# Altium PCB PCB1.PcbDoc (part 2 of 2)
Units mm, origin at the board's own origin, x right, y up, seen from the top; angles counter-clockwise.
Board outline 82.55 x 101.6 mm, 4 copper layers (Top Layer, GND, POWER, Bottom Layer), stack 1.586 mm thick; 125 components, 82 nets, 451 pads, 255 vias.
Unrouted connection lines stored in the file: 4.
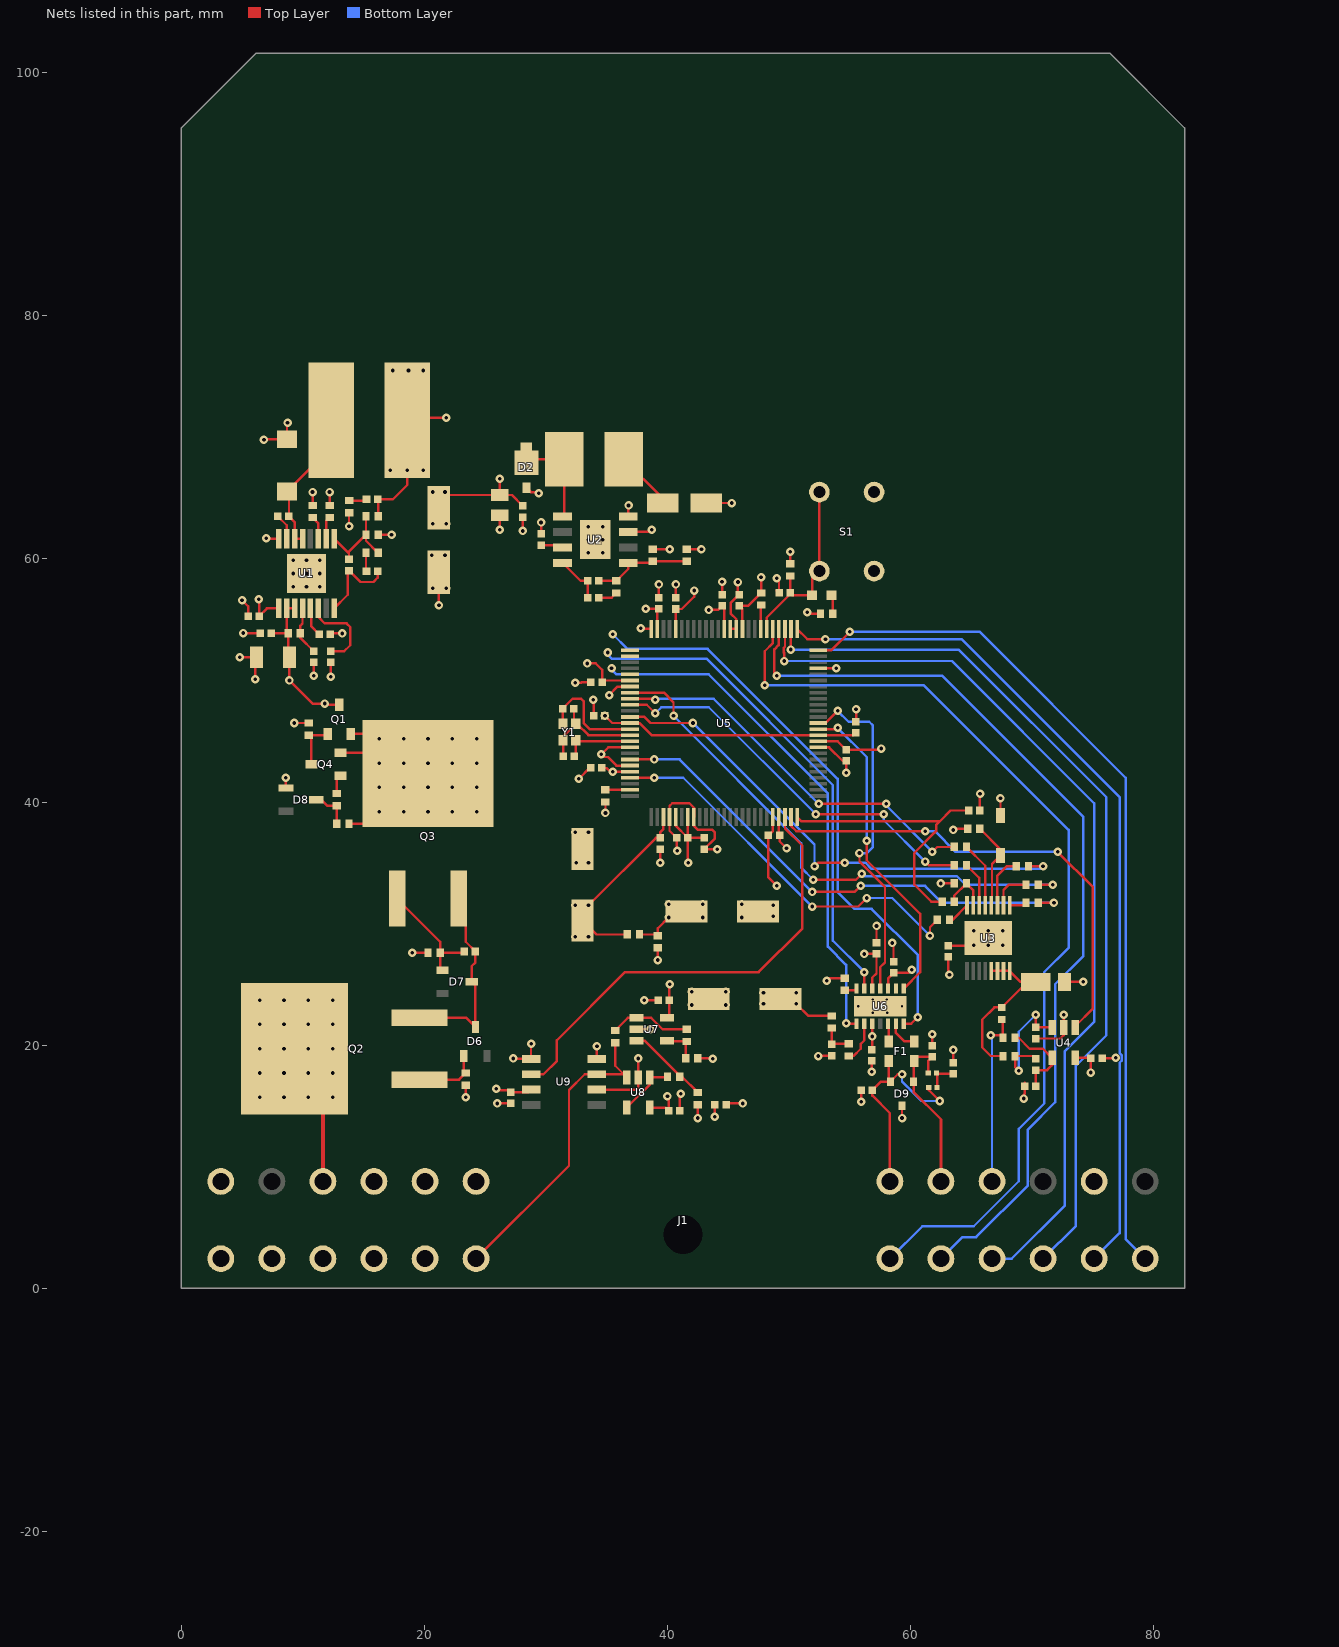
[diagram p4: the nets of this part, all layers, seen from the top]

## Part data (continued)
R31 R32: library part RK73H1HRTTCM60R4F, "Fixed Resistor, Metal Glaze/thick Film, 0.05W, 60.4ohm, 25V, 1% +/-Tol, 300ppm/Cel, Surface Mount, 0201", Manufacturer="KOA Speer", Supplier Part Number=660-RK73H1HRTTCM60R4
R33: library part AC0402FR-076K2L, "Fixed Resistor, Metal Glaze/thick Film, 0.0625W, 6200ohm, 50V, 1% +/-Tol, 100ppm/Cel, Surface Mount, 0402", Case/Package=0402, Manufacturer=Yageo, Max Operating Temperature=155°C, Min Operating Temperature=-55°C, Package Height=0.32mm, Package Length=1mm, Package Shape=Rectangular, Package Width=0.5mm, Power=62.5mW, Rated Temperature=70°C, Resistor Type="FIXED RESISTOR", Supplier Part Number=603-AC0402FR-076K2L, Temperature Coefficient (ppm/Cel)=100, Tolerance=1%, Working Voltage=50V
R34: library part RC0402JR-072KP, "Fixed Resistor, Metal Glaze/thick Film, 0.0625W, 2000ohm, 50V, 5% +/-Tol, 150ppm/Cel, Surface Mount, 0402", Manufacturer=Yageo, Supplier Part Number=603-RC0402JR-072KP
R36 R37: library part AC0402FR-1010RL, "Fixed Resistor, Metal Glaze/thick Film, 0.0625W, 10ohm, 50V, 1% +/-Tol, 200ppm/Cel, Surface Mount, 0402", Case/Package=0402, Manufacturer=Yageo, Max Operating Temperature=155°C, Min Operating Temperature=-55°C, Package Height=0.32mm, Package Length=1mm, Package Shape=Rectangular, Package Width=0.5mm, Power=62.5mW, Rated Temperature=70°C, Resistor Type="FIXED RESISTOR", Supplier Part Number=603-AC0402FR-1010RL, Temperature Coefficient (ppm/Cel)=200, Tolerance=1%, Working Voltage=50V
S1: "BUTON MINI 6X6X5, 4 PINI"
U1: library part A7987TR, "Switching Regulator, Voltage-mode, 4.4A, 1650kHz Switching Freq-Max, PDSO16", Manufacturer=STMicroelectronics, Supplier Part Number=511-A7987TR
U2: library part A7985ATR, "Switching Regulator, Voltage-mode, 3.5A, 275kHz Switching Freq-Max, PDSO8", Case/Package=HLSOP, Frequency=275kHz, Manufacturer=STMicroelectronics, Max Operating Temperature=125°C, Max Output current=3.5A, Max Supply Voltage=38V, Min Input Voltage=4.5V, Min Operating Temperature=-40°C, Nominal Supply Voltage=12V, Package Body Material=Plastic, Package Equivalence Code=SOP8,.25, Package Shape=Rectangular, Package Style="SMALL OUTLINE, HEAT SINK/SLUG, LOW PROFILEMeter", Supplier Part Number=511-A7985ATR, Temperature Grade=AUTOMOTIVE
U3: library part VND7020AJTR, "Buffer/Inverter Based Peripheral Driver, PDSO16", Case/Package=HLSSOP, Manufacturer=STMicroelectronics, Max Operating Temperature=125°C, Max Supply Voltage=28V, Min Operating Temperature=-40°C, Min Supply Voltage=4V, Nominal Supply Voltage=13V, Output Current Flow Direction=SINK, Package Body Material=Plastic, Package Shape=Rectangular, Package Style="SMALL OUTLINE, HEAT SINK/SLUG, LOW PROFILE, SHRINK PITCHMeter", Supplier Part Number=511-VND7020AJTR, Temperature Grade=AUTOMOTIVE
U4: library part INA193AQDBVRQ1, "Operational Amplifier, 1 Func, PDSO5", Case/Package=LSSOP, Manufacturer="Texas Instruments", Max Operating Temperature=125°C, Max Supply Voltage=18V, Min Operating Temperature=-40°C, Min Supply Voltage=2.7V, Nominal Supply Voltage=12V, Package Body Material=Plastic, Package Equivalence Code=TSOP5/6,.11,37, Package Shape=Rectangular, Package Style="SMALL OUTLINE, LOW PROFILE, SHRINK PITCHMeter", Peak Reflow Temperature (Cel)=260°C, Supplier Part Number=595-INA193AQDBVRQ1, Supply Current-Max (Isup)=1.25mA, Temperature Grade=AUTOMOTIVE
U5: library part TMS5700332BPZQQ1, "RISC Microcontroller, 32-Bit, FLASH, CORTEX-R4F CPU, 80MHz, CMOS, PQFP100", Manufacturer="Texas Instruments", Supplier Part Number=595-TMS5700332BPZQQ1
U6: library part TCAN1043DMTRQ1, "Ethernet Transceiver, 1-Trnsvr, PDSO14", Manufacturer="Texas Instruments", Supplier Part Number=595-TCAN1043DMTRQ1
U7 U8: library part AD8538AUJZ-REEL7, "Operational Amplifier, 1 Func, 30uV Offset-Max, CMOS, PDSO5", Average Bias Current-Max (IIB)=100pA, Bias Current-Max (IIB) @25C=25pA, Case/Package=VSSOP, Frequency Compensation=YES, Input Offset Voltage-Max=30uV, Manufacturer="Analog Devices", Max Operating Temperature=125°C, Max Supply Current=215uA, Micropower=Yes, Min Operating Temperature=-40°C, Neg Supply Voltage Limit-Max=0V, Nominal Supply Voltage=5V, Package Body Material=Plastic, Package Equivalence Code=TSOP5/6,.11,37, Package Shape=Rectangular, Package Style="SMALL OUTLINE, VERY THIN PROFILE, SHRINK PITCHMeter", Peak Reflow Temperature (Cel)=260°C, Power=No, Power Supplies=+-1.35/+-2.5/2.7/5V, Supplier Part Number=584-AD8538AUJZ-R7, Supply Voltage Limit-Max=6V, Temperature Grade=AUTOMOTIVE, Time @ Peak Reflow Temperature-Max (s)=40s, Voltage Gain-Min=178000
U9: library part MAX4194ESA+, "Instrumentation Amplifier, 1 Func, 690uV Offset-Max, 0.25MHz Band Width, PDSO8", Average Bias Current-Max (IIB)=20nA, Case/Package=SOP, Input Offset Current-Max (IIO)=3nA, Input Offset Voltage-Max=690uV, Manufacturer=Maxim, Max Operating Temperature=85°C, Max Supply Current=110uA, Min Operating Temperature=-40°C, Nominal Supply Voltage=5V, Package Body Material=Plastic, Package Equivalence Code=SOP8,.25, Package Shape=Rectangular, Package Style="SMALL OUTLINEMeter", Peak Reflow Temperature (Cel)=260°C, Power Supplies=+-1.35/+-3.75/2.7/7.5V, Supplier Part Number=700-MAX4194ESA, Supply Voltage Limit-Max=8V, Temperature Grade=INDUSTRIAL, Time @ Peak Reflow Temperature-Max (s)=30s, Voltage Gain-Max=10000, Voltage Gain-Min=1
Y1: library part ECS-160-10-37B2-CTN-TR, "Crystal 16MHz 10pF 4-Pin SMD ECX-1637B2 T/R", Manufacturer="ECS International", Supplier Part Number=520-160-10-37B2CTNTR

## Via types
v1: diameter 0.7, hole 0.3, Top Layer to Bottom Layer, tented top, 188 vias
v2: diameter 0.7, hole 0.3, Top Layer to Bottom Layer, 61 vias
v3: diameter 0.5, hole 0.2, Top Layer to Bottom Layer, 6 vias

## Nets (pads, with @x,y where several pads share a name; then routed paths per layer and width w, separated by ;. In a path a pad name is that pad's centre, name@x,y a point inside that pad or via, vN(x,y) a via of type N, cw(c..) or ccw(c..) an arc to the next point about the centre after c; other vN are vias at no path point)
1V2: C22.2 C23.2 C27.1 C30.2 C31.2 C33.2 C44.2 C47.2 R25.1 R26.2 U5.13 U5.21 U5.30 U5.32 U5.61 U5.88 U5.99 | length 40.7
  Top Layer w0.2: C33.2@34.6,42.8 35,42.8 35.301,42.499 35.499,42.499 v1(35.5,42.5) 35.501,42.499 U5.21@36.932,42.499 ; v1(34.86,47.1) 35.461,46.499 U5.13@36.932,46.499 37.701,46.499 38.701,45.499 U5.61@52.408,45.499 55.299,45.499 C31.2@55.5,45.7 ; R25.1@37.7,29.1 39.1,29.1 R26.2@39.2,29 39.2,29.6 v1(40.1,30.5) ; v1(38.2,55.9) C23.2@39.3,55.9 39.17,55.77 U5.99@39.17,54.237 ; U5.30@40.67,38.761 40.67,38.056 C44.2@41.67,37.056 ; U5.32@41.67,38.761 C44.2@41.67,37.056 ; v1@41.681,34.8 C44.2@41.681,37.045 ; C47.2@43.028,37.045 C44.2@41.681,37.045 ; v1(43.4,55.8) 44.16,55.8 C22.2@44.5,56.14 44.67,55.97 U5.88@44.67,54.237 ; C44.2@41.67,37.056 C44.2@41.681,37.045
  other v1: 42.9,30.5 40.1,31.6 42.9,31.6 41.7,35
3V3: C21.2 C24.2 C25.1 C26.2 C29.2 C32.2 C37.2 C40.2 C41.2 C49.2 C50.2 C51.2 C52.2 R8.2 R23.2 R24.2 R25.2 R27.2 R40.2 U4.5 U5.6 U5.28 U5.46 U5.60 U5.85 U5.96 U6.5 U7.5 U8.5 U9.7 | length 62.4
  Top Layer w0.2: v1(25.9,16.4) 26,16.3 26.92,16.3 C52.2@27.1,16.12 28.566,16.12 U9.7@28.776,16.33 ; v1(33.4,51.4) 34.1,51.4 34.62,50.88 C29.2@34.62,49.846 34.773,49.999 U5.6@36.932,49.999 ; v1(33.5,31.5) 39.045,37.045 C40.2@39.395,37.045 39.395,37.495 39.67,37.77 U5.28@39.67,38.761 ; C25.1@33.675,31.325 33,30.649 C25.1@33,30.25 34.15,29.1 R25.2@36.7,29.1 ; U8.5@38.55,14.85 39.85,14.85 C51.2@40.1,14.6 40.1,15.7 v1(40,15.8) ; R8.2@38.8,60.8 v1(40.2,60.8) ; U7.5@39.95,22.25 40.16,22.46 C49.2@40.16,23.7 40.16,24.96 v1(40.2,25) ; U5.96@40.67,54.237 40.67,55.85 C26.2@40.7,55.88 41.18,55.88 42.2,56.9 v1(42.2,57.4) ; v1(42.5,14) R40.2@42.5,15.1 ; v1(43.9,14.1) C50.2@43.9,15.1 ; U5.85@46.17,54.237 46.17,55.87 C24.2@45.9,56.14 46.64,56.14 R27.2@47.7,57.2 v1(47.7,58.5) ; U5.46@48.67,38.761 48.67,37.612 C41.2@48.305,37.248 48.305,33.795 v1(49,33.1) ; R24.2@50.1,59.6 v1(50.1,60.6) ; v1@51.6,55.5 R23.2@52.6,55.5 ; U5.60@52.408,44.999 54.001,44.999 C32.2@54.7,44.3 57.5,44.3 v1(57.6,44.4) ; v1(56.2,27.5) C37.2@57.2,27.5 57.2,25.9 56.85,25.55 U6.5@56.85,24.65 ; U4.5@73.55,18.95 74.79,18.95 C21.2@74.84,18.9 v1(74.84,17.74)
  other v1: 32.4,28.9 33.5,28.9 32.4,31.5 51.5,55.6
5V: C1.1 C6.1 C7.2 C11.1 C12.2 C46.2 L1.2 R2.2 U1.1 U2.8 U6.3 | length 29.9
  Top Layer w0.2: v1@6.42,56.68 C6.1@6.42,55.3 7.045,55.925 U1.1@8.025,55.925 ; R2.2@16.2,63.5 16.2,64.86 C7.2@16.16,64.9 17.4,64.9 18.6,66.1 L1.2@18.6,71.4 18.8,71.6 v1(21.8,71.6) ; v1(20.7,65.5) 21.2,65 C1.1@21.2,64.2 ; v1(21.7,65.5) 21.94,65.26 C12.2@26.2,65.26 ; v1(26.2,66.6) C12.2@26.2,65.26 ; C11.1@28.1,64.36 27.2,65.26 C12.2@26.2,65.26 ; U2.8@36.789,63.49 36.789,64.389 v1(36.8,64.4) ; U6.3@58.15,24.65 58.15,25.49 C46.2@58.6,25.94 59.84,25.94 v1(60.1,26.2)
  other v1: 6.383,56.695 20.7,62.9 21.8,62.9 17.2,67.3 18.6,67.3 19.9,67.3 17.4,75.5 18.7,75.5 19.9,75.5
12V: C3.2 C4.2 C16.2 C34.2 C39.1 Q1.3 R1.2 R28.2 U1.2 U1.3 U3.17 U6.10 | length 20.5
  Top Layer w0.2: C4.2@7.4,53.9 R1.2@8.8,53.9 ; U1.3@9.325,55.925 U1.2@8.675,55.925 8.675,54.025 R1.2@8.8,53.9 ; Q1.3@13,48 11.9,48 v1(11.8,48.1) 10.8,48.1 v1(8.9,50) C3.2@8.9,51.9 8.8,52 R1.2@8.8,53.9 ; v1(50.6,23.4) 51.6,22.4 R28.2@53.5,22.4 ; C34.2@56.8,19.62 56.85,19.67 U6.10@56.85,21.75 ; C16.2@63.119,28.19 65.19,28.19 v2(65.2,28.2)
  other v1: 56.85,20.71 47.9,23.4 47.9,24.3 50.6,24.3
  other v2: 66.4,28.2 67.6,28.2 65.2,29.4 66.4,29.4 67.6,29.4
ADCIN0: C17.2 R17.1 U5.50 | length 23.6
  Top Layer w0.2: U5.50@50.67,38.761 51.031,38.4 62.4,38.4 ; R17.1@62.6,31.8 61.7,31.8 60.3,33.2 60.3,35.8 62.1,37.6 62.1,38.1 62.4,38.4 ; C17.2@64.78,39.3 63.3,39.3 62.4,38.4
ADCIN1: U4.1 U5.49 | length 39.8
  Top Layer w0.2: U5.49@50.17,38.761 50.17,38.442 50.17,38.03 50.6,37.6 50.9,37.6 v1(61.2,37.6) ; v1(72.1,35.9) 75,33 75,23 73.55,21.55 U4.1@73.55,21.45
  Bottom Layer w0.2: v1(61.2,37.6) 62,37.6 63.7,35.9 v1(72.1,35.9)
ADCIN9: U5.48 U9.6 | length 38
  Top Layer w0.2: U9.6@28.776,17.6 29.8,17.6 30.9,18.7 30.9,20.4 36.5,26 47.5,26 51.1,29.6 51.1,36.4 49.67,37.83 U5.48@49.67,38.761
CAN_N: C53.1 D9.1 F1.3 J1.B1 R32.1 | length 18.7
  Top Layer w0.2: F1.3@58.2,18.7 58.2,17.15 D9.1@58.35,17 ; J1.B1@58.305,8.78 58.305,14.395 56.86,15.84 C53.1@56.86,16.3 57.56,17 D9.1@58.35,17 ; v1(59.3,17.6) 58.95,17.6 D9.1@58.35,17 ; R32.1@61.5,16.5 61.5,16.3 v1(62.4,15.4)
  Bottom Layer w0.2: v1(59.3,17.6) 59.3,17 60.9,15.4 v1(62.4,15.4)
CAN_P: C54.2 D9.2 F1.2 J1.B2 R31.2 | length 14
  Top Layer w0.2: R31.2@61.46,17.7 61.46,18.7 C54.2@61.8,19.04 60.64,19.04 F1.2@60.3,18.7 60.25,18.65 D9.2@60.25,17 60.25,16.15 62.505,13.895
  Top Layer w0.25: J1.B2@62.505,8.78 62.505,13.895
EN: U5.2 U6.6 | length 41
  Top Layer w0.2: U6.6@56.2,24.65 v1(56.2,26)
  Bottom Layer w0.2: v1(35.1,52.3) 35.1,52.1 35.4,51.8 43.2,51.8 53.6,41.4 53.6,28.6 v1(56.2,26)
F\A\U\L\T\: R11.1 U5.8 | length 44.7
  Top Layer w0.2: U5.8@36.932,48.999 39.701,48.999 40.5,48.2 v1(40.5,47.1) ; v1(52,33.6) 55.5,33.6 v1(56,34.1) ; R11.1@70.5,33.2 v1(71.7,33.2)
  Bottom Layer w0.2: v1(40.5,47.1) 51,36.6 51,34.6 v1(52,33.6) ; v1(56,34.1) 56.2,33.9 63.8,33.9 64.5,33.2 v1(71.7,33.2)
GND: C1.2 C3.1 C4.1 C5.1 C6.2 C10.1 C11.2 C12.1 C13.2 C16.1 C17.1 C18.1 C20.2 C21.1 C22.1 C23.1 C24.1 C25.2 C26.1 C27.2 C28.1 C29.1 C30.1 C31.1 C32.1 C33.1 C34.1 C35.2 C36.1 C37.1 C38.2 C39.2 C40.1 C41.1 C42.1 C44.1 C46.1 C47.1 C49.1 C50.1 C51.1 C52.1 C53.2 C54.1 D1.2 D2.1 D3.1 D4.2 D8.1 D9.3 J1.A2 J1.A3 J1.A4 J1.A5 J1.A6 J1.A7 J1.A10 J1.A11 J1.A12 J1.B5 R3.1 R5.1 R6.1 R7.1 R10.1 R18.1 R19.1 R26.1 R29.1 R33.2 R36.1 R37.1 R39.2 R43.1 S1.1 S1.2 U1.16 U1.17 U2.7 U2.9 U4.2 U5.7 U5.17 U5.20 U5.29 U5.33 U5.47 U5.59 U5.72 U5.86 U5.87 U5.100 U6.2 U6.15 U7.2 U8.2 U9.2 U9.4 U9.5 | length 122.5
  Top Layer w0.2: v1(4.8,51.9) C3.1@6.18,51.9 6.1,51.82 v1(6.1,50.1) ; v1(5,56.6) 5.5,56.1 C6.2@5.5,55.3 ; v1(5.1,53.9) C4.1@6.48,53.9 ; v1@6.85,69.85 D1.2@8.7,69.85 v1@8.7,71.1 ; v1@7.125,61.675 U1.16@8.025,61.675 ; v1(8.6,42) 8.611,41.989 D8.1@8.611,41.15 ; v1(9.3,46.5) R33.2@10.5,46.5 ; R6.1@10.8,64.4 v1(10.8,65.5) ; v1(10.9,50.4) C5.1@10.9,51.48 ; R5.1@12.2,64.4 v1(12.2,65.5) ; C36.1@12.26,53.8 12.36,53.9 v1@13.213,53.9 ; v1(12.3,50.3) C10.1@12.3,51.48 ; v1(13.8,62.7) R3.1@13.8,63.8 ; R7.1@16.2,62 v1(17.3,62) ; v1(19,27.6) R37.1@20.3,27.6 ; v1(21.2,56.2) C1.2@21.2,58.9 ; v1(23.4,15.7) R36.1@23.4,16.7 ; v1@26.1,15.2 C52.1@27.1,15.2 ; v1(26.2,62.4) C12.1@26.2,63.6 ; v1@27.47,18.87 U9.5@28.776,18.87 v1@28.776,20.076 ; v1(28.1,62.3) C11.2@28.1,63.44 ; D2.1@28.4,65.86 28.76,65.5 29.3,65.5 v1(29.4,65.4) ; C35.2@29.6,62.06 v1(29.6,63) ; v1(32.4,49.8) 32.9,49.8 32.946,49.846 C29.1@33.7,49.846 ; v1(32.7,41.9) 33.6,42.8 C33.1@33.68,42.8 ; C30.1@33.94,47.1 v1@33.94,48.36 ; U9.2@34.2,16.33 37.43,16.33 37.6,16.5 U8.2@37.6,17.35 v1(37.6,18.9) ; U9.4@34.2,18.87 v1(34.2,19.9) ; v1(34.548,43.921) 35.126,44.499 U5.17@36.932,44.499 ; v1@34.6,43.7 35.1,43.7 35.801,42.999 U5.20@36.932,42.999 ; v1(34.9,39.1) R29.1@34.9,40 ; v1(35.212,48.778) 35.212,48.812 35.899,49.499 U5.7@36.932,49.499 ; U2.7@36.969,62.4 U2.7@36.789,62.22 38.52,62.22 v1(38.7,62.4) ; U7.2@37.45,21.3 v1(38.6,21.3) ; v1(37.8,54.3) 37.863,54.237 U5.100@38.67,54.237 ; v1(38.1,23.7) C49.1@39.24,23.7 ; v1(39.2,27) R26.1@39.2,28 ; C23.1@39.3,56.82 v1(39.3,57.9) ; v1@39.395,35.005 C40.1@39.395,36.125 ; C26.1@40.7,56.8 v1(40.7,57.9) ; v1@40.761,36.061 C44.1@40.761,37.045 40.17,37.636 U5.29@40.17,38.761 40.17,39.67 40.4,39.9 41.8,39.9 42.2,39.5 42.2,38.791 U5.33@42.17,38.761 42.17,38.03 42.5,37.7 43.7,37.7 43.9,37.5 43.9,36.997 C47.1@43.028,36.125 44.075,36.125 v1(44.1,36.1) ; C51.1@41.1,14.68 C51.1@41.02,14.6 41.02,15.92 v1(41.1,16) ; R10.1@41.6,60.8 v1(42.8,60.8) ; R39.2@42.5,18.9 v1@43.8,18.9 ; C13.2@43.2,64.6 v1(45.3,64.6) ; C22.1@44.5,57.06 v1@44.5,58.1 ; C50.1@44.82,15.1 44.92,15.2 v1(46.2,15.2) ; U5.87@45.17,54.237 U5.86@45.67,54.237 45.67,55.03 45.2,55.5 45.2,56.36 C24.1@45.9,57.06 45.8,57.16 v1(45.8,58.1) ; C28.1@49,57.38 C28.1@49.18,57.2 49.18,58.22 v1(49,58.4) ; U5.47@49.17,38.761 49.17,37.303 C41.1@49.225,37.248 49.225,36.775 v1(49.8,36.2) ; v1@52.34,19.14 C42.1@53.5,19.14 ; U5.59@52.408,44.499 53.301,44.499 54.42,43.38 C32.1@54.7,43.38 v1(54.7,42.4) ; U5.72@52.408,50.999 52.409,51 v1(53.9,51) ; v1(53.1,25.3) 53.3,25.5 R43.1@54.6,25.5 ; C31.1@55.516,46.64 v1(55.516,47.62) ; v1(55.94,15.34) C53.2@55.94,16.3 ; v1(56.8,17.8) C34.1@56.8,18.7 ; C37.1@57.2,28.42 v1(57.2,29.8) ; v1(58.5,28.4) 58.6,28.3 C46.1@58.6,26.86 ; v1(59.3,14) D9.3@59.3,15 ; C54.1@61.8,19.96 v1(61.8,20.9) ; v1(62.5,33.3) R18.1@63.6,33.3 ; C16.1@63.119,27.27 63.119,25.881 v1(63.2,25.8) ; C38.2@63.5,18.56 v1(63.5,19.6) ; v1@63.6,37.8 R19.1@64.7,37.8 ; C17.1@65.7,39.3 v1@65.7,40.7 ; D3.1@67.4,38.9 v1(67.4,40.3) ; v1@69.3,15.9 69.38,15.98 C20.2@69.38,16.6 C20.2@69.38,16.9 ; C18.1@70.3,20.54 72.315,20.54 72.6,20.825 U4.2@72.6,21.45 v1(72.6,22.5) ; D4.2@72.675,25.2 v1(74.2,25.2) ; C21.1@75.76,18.9 v1@76.6,18.9
  other v1: 26,15.2 69.3,15.6 43.718,18.875 27.3,18.9 76.893,18.944 52.4,19.1 28.8,20.1 42,23.3 44.8,23.3 42,24.4 44.8,24.4 46.1,30.5 48.7,30.6 48.7,31.5 46.1,31.6 32.5,35 33.5,35 39.4,35 40.8,36 32.4,37.5 33.5,37.5 63.5,37.7 65.718,40.675 33.9,48.4 13.243,53.865 20.7,57.6 21.8,57.6 44.492,58.12 20.6,60.3 21.7,60.3 7,61.7 6.8,69.8 8.742,71.206
  other v2: 9.2,57.7 10.3,57.7 11.4,57.7 9.2,58.8 10.3,58.8 11.4,58.8 9.2,59.9 10.3,59.9 11.4,59.9 33.477,60.51 34.677,60.51 33.477,61.585 34.677,61.585 33.477,62.66 34.677,62.66
  other v3: 56.9,22.65 58.1,22.65 55.7,23.2 59.3,23.2 56.9,23.75 58.05,23.75
IN0: R12.1 U5.19 | length 41.5
  Top Layer w0.2: U5.19@36.932,43.499 U5.19@36.932,43.499 v1(38.9,43.5) ; v1(51.9,32.6) 55.4,32.6 v1(55.9,33.1) ; R12.1@70.5,31.7 v1(71.8,31.7)
  Bottom Layer w0.2: v1(38.9,43.5) 41,43.5 v1(51.9,32.6) ; v1(55.9,33.1) 61.2,33.1 62.6,31.7 v1(71.8,31.7)
IN1: R13.1 U5.22 | length 32.2
  Top Layer w0.2: U5.22@36.932,41.999 U5.22@36.932,41.999 v1(38.9,42) ; v1(51.9,31.4) 55.7,31.4 v1(56.4,32.1) ; v1(61.6,29) 61.6,29.7 R13.1@62.2,30.3
  Bottom Layer w0.2: v1(38.9,42) 41.3,42 v1(51.9,31.4) ; v1(56.4,32.1) 58.5,32.1 v1(61.6,29)
INH: R43.2 U6.7 | length 1
  Top Layer w0.2: R43.2@54.6,24.5 55.4,24.5 U6.7@55.55,24.65
KGND: C43.1 C45.1 U5.15 Y1.2 Y1.4 | length 9.3
  Top Layer w0.2: C43.1@31.417,43.75 31.417,45.068 Y1.2@31.403,45.082 31.403,45.382 Y1.4@32.453,46.432 ; C45.1@32.309,47.687 32.309,46.576 Y1.4@32.453,46.432 ; U5.15@36.932,45.499 33.501,45.499 32.568,46.432 Y1.4@32.453,46.432
nERROR: R27.1 U5.82 | length 2
  Top Layer w0.2: U5.82@47.67,54.237 47.67,56.17 R27.1@47.7,56.2
NetC2_1: C2.1 U1.15 | length 2.1
  Top Layer w0.2: C2.1@7.94,63.5 8.675,62.765 U1.15@8.675,61.675
NetC2_2: C2.2 D1.1 L1.1 U1.13 U1.14 | length 12.1
  Top Layer w0.2: U1.13@9.975,61.675 U1.14@9.325,61.675 9.325,63.035 C2.2@8.86,63.5 8.86,65.39 D1.1@8.7,65.55 12.35,69.2 L1.1@12.35,71.4
NetC5_2: C5.2 R1.1 U1.4 | length 4.1
  Top Layer w0.2: U1.4@9.975,55.925 9.975,54.675 9.8,54.5 R1.1@9.8,53.9 9.8,53.5 C5.2@10.9,52.4
NetC7_1: C7.1 R3.2 | length 1.5
  Top Layer w0.2: R3.2@13.8,64.8 15.14,64.8 C7.1@15.24,64.9
NetC8_1: C8.1 C9.2 U1.8 | length 7.1
  Top Layer w0.2: U1.8@12.575,55.925 13.7,57.05 13.7,58.94 C9.2@13.8,59.04 14.74,58.1 15.8,58.1 16.16,58.46 C8.1@16.16,59
NetC8_2: C8.2 R4.1 | length 1.5
  Top Layer w0.2: R4.1@15.2,60.5 15.2,59.04 C8.2@15.24,59
NetC9_1: C9.1 R2.1 R4.2 R7.2 U1.9 | length 7.8
  Top Layer w0.2: U1.9@12.575,61.675 13.8,60.45 ; C9.1@13.8,59.96 13.8,60.45 ; R2.1@15.2,63.5 R7.2@15.2,62 ; R4.2@16.2,60.5 15.2,61.5 R7.2@15.2,62 ; 13.8,60.45 13.8,60.6 R7.2@15.2,62
NetC10_2: C10.2 U1.6 | length 7
  Top Layer w0.2: U1.6@11.275,55.925 11.275,55.225 11.8,54.7 13.6,54.7 13.9,54.4 13.9,52.9 13.4,52.4 C10.2@12.3,52.4
NetC13_1: C13.1 L2.2 | length 4.9
  Top Layer w0.2: L2.2@36.4,68.2 39.6,65 C13.1@39.6,64.6
NetC14_1: C14.1 C15.1 U2.4 | length 4.1
  Top Layer w0.2: U2.4@31.365,59.68 32.846,58.2 C14.1@33.44,58.2 C15.1@33.44,56.8
NetC14_2: C14.2 R8.1 R9.2 R10.2 U2.5 | length 8.2
  Top Layer w0.2: C14.2@34.36,58.2 R9.2@35.8,58.2 36.789,59.189 U2.5@36.789,59.68 38.68,59.68 R8.1@38.8,59.8 40.4,59.8 R10.2@41.6,59.8
NetC15_2: C15.2 R9.1 | length 1.6
  Top Layer w0.2: C15.2@34.36,56.8 35.4,56.8 R9.1@35.8,57.2
NetC18_2: C18.2 C19.1 R21.1 U4.3 | length 10.7
  Top Layer w0.2: v1(68.9,17.9) 68.6,18.2 R21.1@68.6,19.1 70.06,19.1 C19.1@70.3,18.86 ; v1(70.3,22.5) C18.2@70.3,21.46 70.31,21.45 U4.3@71.65,21.45
  Bottom Layer w0.2: v1(68.9,17.9) 68.9,21.1 v1(70.3,22.5)
NetC19_2: C19.2 C20.1 R22.1 U4.4 | length 6.9
  Top Layer w0.2: R22.1@68.6,20.6 68.9,20.6 69.8,19.7 70.9,19.7 U4.4@71.65,18.95 71.65,18.35 71.24,17.94 C19.2@70.3,17.94 C20.1@70.3,16.9
NetC35_1: C35.1 U2.3 | length 1.8
  Top Layer w0.2: C35.1@29.6,61.14 31.176,61.14 U2.3@31.365,60.95
NetC36_2: C36.2 U1.5 | length 2.4
  Top Layer w0.2: U1.5@10.625,55.925 10.7,55.85 10.7,54.44 C36.2@11.34,53.8
NetC38_1: C38.1 R31.1 R32.2 | length 2.5
  Top Layer w0.2: R31.1@62.14,17.7 R31.1@62.18,17.66 ; R32.2@62.18,16.5 R31.1@62.18,17.66 ; C38.1@63.5,17.64 62.2,17.64 R31.1@62.18,17.66
NetC42_2: C42.2 R28.1 R30.2 | length 2.8
  Top Layer w0.2: R28.1@53.5,21.4 C42.2@53.5,20.06 53.54,20.1 R30.2@54.9,20.1
NetC48_1: C48.1 D7.1 Q3.1 R37.2 | length 9.5
  Top Layer w0.2: Q3.1@17.76,32.045 21.3,28.505 R37.2@21.3,27.6 ; D7.1@21.5,26.155 21.3,26.355 R37.2@21.3,27.6 ; C48.1@23.28,27.7 23.18,27.6 R37.2@21.3,27.6
NetC48_2: C48.2 D6.3 D7.3 Q2.3 Q3.3 | length 16.3
  Top Layer w0.2: Q2.3@19.61,22.24 23.46,22.24 D6.3@24.2,21.5 24.2,24.9 D7.3@23.9,25.2 23.9,26.5 24.2,26.8 C48.2@24.2,27.7 23.4,28.5 23.4,31.485 Q3.3@22.84,32.045
NetD2_2: D2.2 D2.3 L2.1 U2.1 | length 8
  Top Layer w0.2: D2.2@28.4,67.915 28.685,68.2 L2.1@31.5,68.2 31.5,63.625 U2.1@31.365,63.49
NetD3_2: D3.2 R19.2 U3.4 | length 7.3
  Top Layer w0.2: R19.2@65.7,37.8 67.4,36.1 D3.2@67.4,35.6 66.7,34.9 66.7,31.55 U3.4@66.65,31.5
NetD5_2: D5.2 R23.1 | length 1.5
  Top Layer w0.2: D5.2@53.5,57 53.6,56.9 R23.1@53.6,55.5
NetD6_1: D6.1 Q2.1 R36.2 | length 5.5
  Top Layer w0.2: Q2.1@19.61,17.16 22.86,17.16 R36.2@23.4,17.7 23.245,17.855 D6.1@23.245,19.1
NetD8_3: D8.3 R34.1 R35.1 | length 3.4
  Top Layer w0.2: D8.3@11.1,40.2 11.5,40.2 12,39.7 R35.1@12.8,39.7 R34.1@12.8,38.2
NetF1_1: F1.1 U6.13 | length 2.5
  Top Layer w0.2: U6.13@58.8,21.75 58.8,21 59.5,20.3 F1.1@60.3,20.3
NetF1_4: F1.4 U6.12 | length 1.5
  Top Layer w0.2: U6.12@58.15,21.75 58.2,21.7 F1.4@58.2,20.3
NetQ1_1: Q1.1 Q4.3 R33.1 | length 4.1
  Top Layer w0.2: Q4.3@10.7,43.1 10.7,45.3 R33.1@10.5,45.5 11.95,45.5 Q1.1@12.05,45.6
NetQ1_2: Q1.2 Q3.2 Q4.2 R34.2 | length 13.3
  Top Layer w0.2: Q4.2@13.1,44.05 18.605,44.05 Q3.2@20.3,42.355 ; R34.2@13.8,38.2 15.3,38.2 v2(16.3,39.2) ; Q1.2@13.95,45.6 15.9,45.6 v2(16.3,45.2)
  other v2: 18.3,39.2 20.3,39.2 22.3,39.2 24.3,39.2 16.3,41.2 18.3,41.2 20.3,41.2 22.3,41.2 24.3,41.2 16.3,43.2 18.3,43.2 20.3,43.2 22.3,43.2 24.3,43.2 18.3,45.2 20.3,45.2 22.3,45.2 24.3,45.2
NetQ4_1: Q4.1 R35.2 | length 1.6
  Top Layer w0.2: R35.2@12.8,40.7 12.8,41.85 Q4.1@13.1,42.15
NetR5_2: R5.2 U1.10 | length 1.8
  Top Layer w0.2: U1.10@11.925,61.675 11.925,63.125 R5.2@12.2,63.4
NetR6_2: R6.2 U1.11 | length 1.9
  Top Layer w0.2: R6.2@10.8,63.4 11.275,62.925 U1.11@11.275,61.675
NetR11_2: R11.2 U3.2 | length 3.3
  Top Layer w0.2: U3.2@67.65,31.5 67.65,32.75 68.1,33.2 R11.2@69.5,33.2
NetR12_2: R12.2 U3.1 | length 1.4
  Top Layer w0.2: U3.1@68.15,31.5 69.3,31.5 R12.2@69.5,31.7
NetR13_2: R13.2 U3.8 | length 1.9
  Top Layer w0.2: R13.2@63.2,30.3 63.45,30.3 U3.8@64.65,31.5
NetR14_2: R14.2 U3.3 | length 4.3
  Top Layer w0.2: U3.3@67.15,31.5 67.15,33.95 67.9,34.7 R14.2@68.7,34.7
NetR15_2: R15.2 U3.5 | length 5.4
  Top Layer w0.2: R15.2@64.6,36.3 66.15,34.75 U3.5@66.15,31.5
NetR16_2: R16.2 U3.6 | length 3.7
  Top Layer w0.2: R16.2@64.6,34.8 65.65,33.75 U3.6@65.65,31.5
NetR17_2: R17.2 R18.2 U3.7 | length 3.9
  Top Layer w0.2: R17.2@63.6,31.8 63.6,32.3 R18.2@64.6,33.3 65.15,32.75 U3.7@65.15,31.5
NetR29_2: R29.2 U5.24 | length 2
  Top Layer w0.2: R29.2@34.9,41 R29.2@34.9,41 U5.24@36.932,40.999
NetR30_1: R30.1 U6.9 | length 3.4
  Top Layer w0.2: R30.1@54.9,19.1 55.3,19.1 55.9,19.7 55.9,20.1 56.2,20.4 U6.9@56.2,21.75
NetR38_1: R38.1 R41.2 U7.1 | length 6.7
  Top Layer w0.2: R41.2@35.7,21.2 36.75,22.25 U7.1@37.45,22.25 38.65,22.25 39.6,21.3 R38.1@41.6,21.3
NetR38_2: R38.2 R39.1 U7.4 | length 3.1
  Top Layer w0.2: U7.4@39.95,20.35 40,20.3 R38.2@41.6,20.3 41.5,20.2 R39.1@41.5,18.9
NetR40_1: R40.1 R42.2 U7.3 | length 6.9
  Top Layer w0.2: U7.3@37.45,20.35 38.15,20.35 41,17.5 R42.2@41,17.4 41.2,17.4 R40.1@42.5,16.1
NetR42_1: R42.1 U8.1 U8.4 | length 4.8
  Top Layer w0.2: U8.4@36.65,14.85 38.55,16.75 U8.1@38.55,17.35 39.95,17.35 R42.1@40,17.4
nFAULT: U5.5 U6.8 | length 42.5
  Top Layer w0.2: v1(54.7,21.8) 54.75,21.75 U6.8@55.55,21.75
  Bottom Layer w0.2: v1(35.4,51) 35.4,50.9 35.8,50.5 43.4,50.5 53.2,40.7 53.2,28.1 54.7,26.6 v1(54.7,21.8)
nRST: C28.2 D5.1 R24.1 S1.3 S1.4 U5.81 | length 15.8
  Top Layer w0.2: U5.81@48.17,54.237 48.17,55.17 50.1,57.1 C28.2@50.1,57.2 ; R24.1@50.1,58.6 C28.2@50.1,57.2 ; S1.3@52.5,65.5 S1.4@52.5,59 51.9,58.4 D5.1@51.9,57 50.3,57 C28.2@50.1,57.2
nSTB: U5.1 U6.14 | length 48
  Top Layer w0.2: U6.14@59.45,21.75 60.05,21.75 v1(60.6,22.3)
  Bottom Layer w0.2: v1(35.5,53.8) 36.7,52.6 43.3,52.6 54,41.9 54,32.6 55.4,31.2 56.8,31.2 60.6,27.4 v1(60.6,22.3)
NTC+: J1.A1 R41.1 U8.3 U9.3 | length 25.3
  Top Layer w0.2: J1.A1@24.255,2.43 31.9,10.075 31.9,16.3 33.2,17.6 U9.3@34.2,17.6 U8.3@36.4,17.6 ; R41.1@35.7,20.2 35.7,18.3 U8.3@36.4,17.6 ; U8.3@36.65,17.35 U8.3@36.4,17.6
nTRST: J1.B8 U5.76 | length 71.3
  Top Layer w0.2: U5.76@50.67,54.237 51.507,53.4 v1(53,53.4)
  Bottom Layer w0.2: v1(53,53.4) 64.2,53.4 77.2,40.4 77.2,19.344 77.393,19.152 77.393,18.737 77.2,18.545 77.2,4.525 J1.B8@75.105,2.43
OSCIN: C45.2 U5.14 Y1.1 | length 9.2
  Top Layer w0.2: Y1.1@31.403,46.432 31.403,47.673 C45.2@31.389,47.687 32.202,48.5 32.9,48.5 33.1,48.3 33.1,46.5 33.601,45.999 U5.14@36.932,45.999
OSCOUT: C43.2 U5.16 Y1.3 | length 5.9
  Top Layer w0.2: C43.2@32.337,43.75 32.453,43.866 Y1.3@32.453,45.082 32.536,44.999 U5.16@36.932,44.999
PUMP+: D4.1 R20.1 R21.2 U3.13 U3.14 U3.15 U3.16 | length 13.3
  Top Layer w0.2: U3.13@66.65,26.1 U3.14@67.15,26.1 U3.15@67.65,26.1 U3.16@68.15,26.1 69.05,25.2 D4.1@69.6,25.2 ; R21.2@67.6,19.1 66.6,19.1 65.9,19.8 65.9,22.1 66.9,23.1 R20.1@67.5,23.1 D4.1@69.6,25.2 ; D4.1@70.3,25.2 D4.1@69.6,25.2
PUMP_OUT: J1.B3 R20.2 R22.2 | length 15.1
  Top Layer w0.2: v1(66.6,20.8) 67.4,20.8 R22.2@67.6,20.6 67.6,22.3 67.5,22.2 R20.2@67.5,22.1
  Bottom Layer w0.2: v1(66.6,20.8) 66.7,20.8 66.705,20.795 J1.B3@66.705,8.78
RTCK: J1.B12 U5.80 | length 78.7
  Top Layer w0.2: v1(48,49.6) 48,52.4 48.67,53.07 U5.80@48.67,54.237
  Bottom Layer w0.2: v1(48,49.6) 61.1,49.6 73,37.7 73,28 71,26 71,15.2 68.9,13.1 68.9,8.8 65.2,5.1 60.975,5.1 J1.B12@58.305,2.43
RXD: U5.63 U6.4 | length 28.9
  Top Layer w0.2: U5.63@52.408,46.499 52.999,46.499 53.199,46.699 53.207,46.699 53.295,46.787 53.295,46.795 v1(54,47.5) ; v1(55.8,35.8) 55.8,35.1 57.9,33 57.9,26.8 57.5,26.4 U6.4@57.5,24.65
  Bottom Layer w0.2: v1(54,47.5) 54.9,46.6 56.6,46.6 56.907,46.293 56.907,36.3 56.407,35.8 v1(55.8,35.8)
SEL0: R15.1 U5.9 | length 32.2
  Top Layer w0.2: U5.9@36.932,48.499 38.901,48.499 v1(39,48.4) ; v1(52.45,39.85) v1(58,39.85) ; v1(61.8,35.9) 62.2,36.3 R15.1@63.6,36.3
  Bottom Layer w0.2: v1@39,48.5 43.8,48.5 v1(52.45,39.85) ; v1(58,39.85) 58,39.7 v1(61.8,35.9)
SEL1: R16.1 U5.10 | length 32.8
  Top Layer w0.2: U5.10@36.932,47.999 38.301,47.999 v1(39,47.3) ; v1(52.2,39) v1(57.8,39) ; v1(61.2,35.1) 61.5,34.8 R16.1@63.6,34.8
  Bottom Layer w0.2: v1(39,47.3) 39.5,47.8 43.4,47.8 v1(52.2,39) ; v1(57.8,39) 57.8,38.5 v1(61.2,35.1)
SEN: R14.1 U5.12 | length 41.7
  Top Layer w0.2: U5.12@36.932,46.999 38.101,46.999 38.6,46.5 v1(42.1,46.5) ; v1(52.1,34.7) 52.4,35 v1(54.6,35) ; R14.1@69.7,34.7 v1(70.9,34.7)
  Bottom Layer w0.2: v1(42.1,46.5) 52.1,36.5 v1(52.1,34.7) ; v1(54.6,35) 56.3,35 56.8,34.5 70.7,34.5 v1(70.9,34.7)
TCK: J1.B11 U5.79 | length 76
  Top Layer w0.2: v1(49,50.4) 48.8,50.6 48.8,52.553 49.15,52.903 49.17,52.923 U5.79@49.17,54.237
  Bottom Layer w0.2: v1(49,50.4) 62.6,50.4 74.2,38.8 74.2,27.3 71.9,25 71.9,15.3 69.655,13.055 69.655,8.455 65.4,4.2 64.275,4.2 J1.B11@62.505,2.43
TDI: J1.B9 U5.77 | length 72.8
  Top Layer w0.2: v1(50.141,52.541) 50.141,54.208 U5.77@50.17,54.237
  Bottom Layer w0.2: v1@50.141,52.559 v1(50.141,52.541) 63.959,52.541 76.1,40.4 76.1,20.8 73.6,18.3 73.6,5.125 J1.B9@70.905,2.43
TDO: J1.B10 U5.78 | length 74.9
  Top Layer w0.2: v1(49.6,51.6) 49.6,52.262 49.571,52.291 49.571,52.679 49.67,52.777 U5.78@49.67,54.237
  Bottom Layer w0.2: v1(49.6,51.6) 63.4,51.6 75.1,39.9 75.1,21.9 72.7,19.5 72.7,6.8 68.33,2.43 J1.B10@66.705,2.43
TMS: J1.B7 U5.75 | length 71.1
  Top Layer w0.2: U5.75@52.408,52.499 53.499,52.499 v1(55,54)
  Bottom Layer w0.2: v1(55,54) 65.7,54 77.7,42 77.7,4.035 J1.B7@79.305,2.43
TXD: U5.62 U6.1 | length 26.5
  Top Layer w0.2: U5.62@52.408,45.999 53.899,45.999 v1(54,46.1) ; v1(56.4,36.8) 56.4,35.2 60.8,30.8 60.8,26 U6.1@59.45,24.65
  Bottom Layer w0.2: v1(54,46.1) 56.4,43.7 v1(56.4,36.8)
VBAT: J1.A9 Q2.2 | length 11.9
  Top Layer w0.35: Q2.2@9.3,19.7 11.655,17.345 J1.A9@11.655,8.78
  other v2: 6.455,15.7 8.455,15.7 10.455,15.7 12.455,15.7 6.455,17.7 8.455,17.7 10.455,17.7 12.455,17.7 6.455,19.7 8.455,19.7 10.455,19.7 12.455,19.7 6.455,21.7 8.455,21.7 10.455,21.7 12.455,21.7 6.455,23.7 8.455,23.7 10.455,23.7 12.455,23.7
pads on no net: D6.2 D7.2 D8.2 J1.A8 J1.B4 J1.B6 J1.MH1 U1.7 U1.12 U2.2 U2.6 U3.9 U3.10 U3.11 U3.12 U5.3 U5.4 U5.11 U5.18 U5.23 U5.25 U5.26 U5.27 U5.31 U5.34 U5.35 U5.36 U5.37 U5.38 U5.39 U5.40 U5.41 U5.42 U5.43 U5.44 U5.45 U5.51 U5.52 U5.53 U5.54 U5.55 U5.56 U5.57 U5.58 U5.64 U5.65 U5.66 U5.67 U5.68 U5.69 U5.70 U5.71 U5.73 U5.74 U5.83 U5.84 U5.89 U5.90 U5.91 U5.92 U5.93 U5.94 U5.95 U5.97 U5.98 U6.11 U9.1 U9.8
copper on no net:
  other v1: -4.4,56.1

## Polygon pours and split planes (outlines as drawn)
GND on Bottom Layer "NONET_L-01_P-001" (solid, remove dead copper, pour order 1): 0.3,-0.228 82.85,-0.228 82.85,95.228 76.706,101.372 6.444,101.372 0.3,95.228
GND on Top Layer "NONET_L-01_P-001" (solid, remove dead copper, pour order 0): 0.2,-0.2 82.75,-0.2 82.75,95.256 76.606,101.4 6.344,101.4 0.2,95.256
GND on GND (split plane): 82.04,95.245 82.04,0.51 0.51,0.51 0.51,95.245 6.355,101.09 76.195,101.09
1V2 on POWER (split plane): 56.171,49.046 56.171,40.154 50.146,34.129 45.2,34.129 45.15,34.12 45.108,34.092 43.608,32.592 43.58,32.55 43.571,32.5 43.571,27.654 43.346,27.429 35.254,27.429 34.429,28.254 34.429,54.546 36.254,56.371 48.846,56.371
12V on POWER (split plane): 12.471,13 12.48,12.95 12.508,12.908 12.55,12.88 12.6,12.871 47.1,12.871 47.15,12.88 47.192,12.908 47.22,12.95 47.229,13 47.229,25.371 62.3,25.371 62.35,25.38 62.392,25.408 62.42,25.45 62.429,25.5 62.429,26.3 62.429,29.171 68.071,29.171 68.071,14.925 68.05,14.929 49.6,14.929 49.55,14.92 49.508,14.892 49.48,14.85 49.471,14.8 49.471,11.929 8.229,11.929 8.229,15.7 8.229,50.546 8.254,50.571 12.471,50.571
5V on POWER (split plane): 82.04,95.245 82.04,42.929 63.8,42.929 63.75,42.92 63.708,42.892 62.208,41.392 62.18,41.35 62.171,41.3 62.171,29.3 62.171,26.3 62.171,25.654 62.146,25.629 59.254,25.629 59.029,25.854 59.029,65.6 59.02,65.65 58.992,65.692 58.95,65.72 58.9,65.729 42.3,65.729 42.25,65.72 42.208,65.692 31.346,54.829 0.51,54.829 0.51,95.245 6.355,101.09 76.195,101.09
3V3 on POWER (split plane): 58.771,25.8 58.78,25.75 58.808,25.708 58.887,25.629 47.1,25.629 47.05,25.62 47.008,25.592 46.98,25.55 46.971,25.5 46.971,13.129 12.729,13.129 12.729,50.7 12.72,50.75 12.692,50.792 12.65,50.82 12.6,50.829 8.2,50.829 8.15,50.82 8.108,50.792 8.008,50.692 7.98,50.65 7.971,50.6 7.971,15.7 7.971,11.8 7.98,11.75 8.008,11.708 8.05,11.68 8.1,11.671 49.6,11.671 49.65,11.68 49.692,11.708 49.72,11.75 49.729,11.8 49.729,14.671 68.05,14.671 68.1,14.68 68.125,14.697 68.15,14.68 68.2,14.671 68.25,14.68 68.292,14.708 68.32,14.75 68.329,14.8 68.329,29.3 68.32,29.35 68.292,29.392 68.25,29.42 68.2,29.429 62.429,29.429 62.429,41.246 63.854,42.671 82.04,42.671 82.04,0.51 0.51,0.51 0.51,54.571 31.4,54.571 31.45,54.58 31.492,54.608 42.354,65.471 58.771,65.471

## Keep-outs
Keep-Out Layer:
  rectangle: 40.275,91.6 42.275,101.6
  rectangle: 52.553,0 82.553,12
  rectangle: 0,0 30,12
  rectangle: 35.275,-0.09 47.275,8.91
  rectangle: 0.003,98.6 82.553,101.6
  rectangle: 78.557,0 82.557,101.6
  rectangle: 0,0 4,101.6

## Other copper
POWER (plane layer: these items are gaps in the copper):
  lines w0.254: -0.1,54.7 31.4,54.7 42.3,65.6 58.9,65.6 58.9,25.8 59.2,25.5 62.3,25.5 62.3,26.3 62.3,41.3 63.8,42.8 82.4,42.8 ; 68.05,14.8 49.6,14.8 49.6,11.8 8.1,11.8 8.1,15.7 8.1,50.6 8.2,50.7 12.6,50.7 12.6,13 14.1,13 47.1,13 47.1,25.5 51.6,25.5 62.2,25.5 62.3,25.6 62.3,29.3 68.2,29.3 68.2,14.8 ; 34.3,28.2 34.3,54.6 36.2,56.5 37.6,56.5 48.9,56.5 56.3,49.1 56.3,40.1 50.2,34 45.2,34 43.7,32.5 43.7,27.6 43.4,27.3 35.2,27.3 34.3,28.2

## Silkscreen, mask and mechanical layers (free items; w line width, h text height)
Mechanical 1:
  lines w0.254: 0,0 0.127,0
Board Outline:
  lines w0.254: 76.396,101.6 6.515,101.6 6.144,101.6 0,95.456 0,0 82.55,0 82.55,95.456 76.406,101.6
